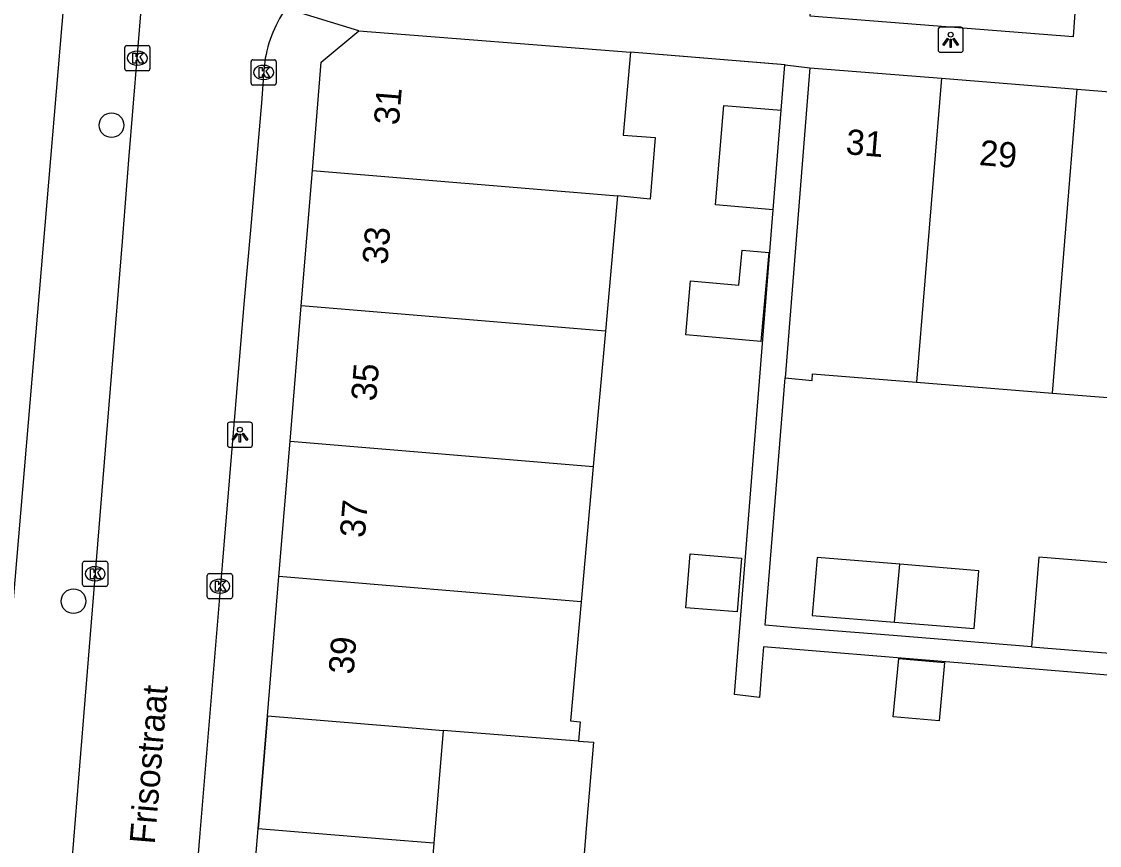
# Model space of a CAD drawing. Extents: x 159961 to 160856, y 382704 to 383353.
# Drawn here: x 160441.41 to 160484.26, y 383165.57 to 383198.31 of the extents above; entities that cross this region are included whole.
import ezdxf

# ---------------------------------------------------------------- set-up
doc = ezdxf.new("R2010")
doc.units = 0
for name, color, linetype in [('IMGEO_Boom', 7, 'Continuous'), ('IMGEO_Kolk', 7, 'Continuous'), ('IMGEO_Lichtpunt', 7, 'Continuous'), ('IMGEO_Muur', 7, 'Continuous'), ('IMGEO_Openbare_ruimte_label', 7, 'Continuous'), ('IMGEO_Pand', 7, 'Continuous'), ('IMGEO_Pand_nummerreeks', 7, 'Continuous'), ('IMGEO_Rijbaan_lokaal_open', 7, 'Continuous'), ('IMGEO_Voetpad_open', 7, 'Continuous')]:
    doc.layers.add(name, color=color, linetype=linetype)

msp = doc.modelspace()

# ---------------------------------------------------------------- linework, layer by layer
at = {"layer": 'IMGEO_Boom'}
for centre in [(160444.987, 383194.191), (160443.476, 383175.277)]:
    msp.add_circle(centre, 0.489, dxfattribs=at)
at = {"layer": 'IMGEO_Kolk'}
for p, q in [((160445.515, 383196.428), (160445.515, 383197.28)), ((160445.59, 383197.354), (160446.442, 383197.354)), ((160446.516, 383197.28), (160446.516, 383196.428)), ((160446.003, 383197.134), (160446.028, 383197.134)), ((160450.608, 383196.788), (160451.46, 383196.788)), ((160446.442, 383196.354), (160445.59, 383196.354)), ((160446.026, 383196.574), (160446.001, 383196.574)), ((160450.533, 383195.862), (160450.533, 383196.714)), ((160451.021, 383196.568), (160451.046, 383196.568)), ((160451.534, 383196.714), (160451.534, 383195.862)), ((160451.044, 383196.008), (160451.019, 383196.008)), ((160451.46, 383195.788), (160450.608, 383195.788)), ((160443.836, 383175.939), (160443.836, 383176.791)), ((160443.911, 383176.865), (160444.763, 383176.865)), ((160444.324, 383176.645), (160444.349, 383176.645)), ((160444.837, 383176.791), (160444.837, 383175.939)), ((160448.794, 383175.447), (160448.794, 383176.299)), ((160448.869, 383176.373), (160449.721, 383176.373)), ((160449.795, 383176.299), (160449.795, 383175.447)), ((160444.763, 383175.865), (160443.911, 383175.865)), ((160444.347, 383176.085), (160444.322, 383176.085)), ((160449.282, 383176.153), (160449.307, 383176.153)), ((160449.721, 383175.373), (160448.869, 383175.373)), ((160449.305, 383175.593), (160449.28, 383175.593))]:
    msp.add_line(p, q, dxfattribs=at)
for points in [[(160445.515, 383196.428), (160445.515, 383197.28)], [(160445.59, 383197.354), (160446.442, 383197.354)], [(160446.516, 383197.28), (160446.516, 383196.428)], [(160445.836, 383197.054), (160445.959, 383197.054), (160445.959, 383196.903), (160446.089, 383197.054), (160446.253, 383197.054), (160446.107, 383196.903), (160446.26, 383196.654), (160446.108, 383196.654), (160446.023, 383196.818), (160445.959, 383196.751), (160445.959, 383196.654), (160445.836, 383196.654), (160445.836, 383197.054)], [(160450.608, 383196.788), (160451.46, 383196.788)], [(160446.442, 383196.354), (160445.59, 383196.354)], [(160450.533, 383195.862), (160450.533, 383196.714)], [(160450.854, 383196.488), (160450.977, 383196.488), (160450.977, 383196.337), (160451.107, 383196.488), (160451.271, 383196.488), (160451.125, 383196.337), (160451.278, 383196.088), (160451.126, 383196.088), (160451.041, 383196.252), (160450.977, 383196.185), (160450.977, 383196.088), (160450.854, 383196.088), (160450.854, 383196.488)], [(160451.534, 383196.714), (160451.534, 383195.862)], [(160451.46, 383195.788), (160450.608, 383195.788)], [(160443.836, 383175.939), (160443.836, 383176.791)], [(160443.911, 383176.865), (160444.763, 383176.865)], [(160444.837, 383176.791), (160444.837, 383175.939)], [(160444.157, 383176.565), (160444.28, 383176.565), (160444.28, 383176.414), (160444.41, 383176.565), (160444.574, 383176.565), (160444.428, 383176.414), (160444.581, 383176.165), (160444.429, 383176.165), (160444.344, 383176.329), (160444.28, 383176.262), (160444.28, 383176.165), (160444.157, 383176.165), (160444.157, 383176.565)], [(160448.794, 383175.447), (160448.794, 383176.299)], [(160448.869, 383176.373), (160449.721, 383176.373)], [(160449.795, 383176.299), (160449.795, 383175.447)], [(160444.763, 383175.865), (160443.911, 383175.865)], [(160449.115, 383176.073), (160449.238, 383176.073), (160449.238, 383175.922), (160449.368, 383176.073), (160449.532, 383176.073), (160449.386, 383175.922), (160449.539, 383175.673), (160449.387, 383175.673), (160449.302, 383175.837), (160449.238, 383175.77), (160449.238, 383175.673), (160449.115, 383175.673), (160449.115, 383176.073)], [(160449.721, 383175.373), (160448.869, 383175.373)]]:
    msp.add_lwpolyline(points, dxfattribs=at)
for centre, start, end in [((160445.592, 383197.278), 91.552, 178.448), ((160445.592, 383197.278), 91.552, 178.448), ((160446.44, 383197.278), 1.552, 88.448), ((160446.44, 383197.278), 1.552, 88.448), ((160450.61, 383196.712), 91.552, 178.448), ((160450.61, 383196.712), 91.552, 178.448), ((160451.458, 383196.712), 1.552, 88.448), ((160451.458, 383196.712), 1.552, 88.448), ((160445.592, 383196.43), 181.552, 268.448), ((160445.592, 383196.43), 181.552, 268.448), ((160446.44, 383196.43), 271.552, 358.448), ((160446.44, 383196.43), 271.552, 358.448), ((160450.61, 383195.864), 181.552, 268.448), ((160450.61, 383195.864), 181.552, 268.448), ((160451.458, 383195.864), 271.552, 358.448), ((160451.458, 383195.864), 271.552, 358.448), ((160443.913, 383176.789), 91.552, 178.448), ((160443.913, 383176.789), 91.552, 178.448), ((160444.761, 383176.789), 1.552, 88.448), ((160444.761, 383176.789), 1.552, 88.448), ((160448.871, 383176.297), 91.552, 178.448), ((160448.871, 383176.297), 91.552, 178.448), ((160449.719, 383176.297), 1.552, 88.448), ((160449.719, 383176.297), 1.552, 88.448), ((160443.913, 383175.941), 181.552, 268.448), ((160443.913, 383175.941), 181.552, 268.448), ((160444.761, 383175.941), 271.552, 358.448), ((160444.761, 383175.941), 271.552, 358.448), ((160448.871, 383175.449), 181.552, 268.448), ((160448.871, 383175.449), 181.552, 268.448), ((160449.719, 383175.449), 271.552, 358.448), ((160449.719, 383175.449), 271.552, 358.448)]:
    msp.add_arc(centre, 0.0765, start, end, dxfattribs=at)
for centre, major_axis, ratio, start_param, end_param in [((160446.002, 383196.854), (-0.387, 0.002), 0.722429, 4.712389, 7.853982), ((160446.027, 383196.854), (-0.39, 0.002), 0.717154, 1.570796, 4.712389), ((160451.02, 383196.288), (-0.387, 0.002), 0.722429, 4.712389, 7.853982), ((160451.045, 383196.288), (-0.39, 0.002), 0.717154, 1.570796, 4.712389), ((160444.323, 383176.365), (-0.387, 0.002), 0.722429, 4.712389, 7.853982), ((160444.348, 383176.365), (-0.39, 0.002), 0.717154, 1.570796, 4.712389), ((160449.281, 383175.873), (-0.387, 0.002), 0.722429, 4.712389, 7.853982), ((160449.306, 383175.873), (-0.39, 0.002), 0.717154, 1.570796, 4.712389)]:
    msp.add_ellipse(centre, major_axis=major_axis, ratio=ratio, start_param=start_param, end_param=end_param, dxfattribs=at)
at = {"layer": 'IMGEO_Lichtpunt'}
for p, q in [((160478.745, 383198.085), (160477.937, 383198.085)), ((160478.745, 383198.085), (160477.937, 383198.085)), ((160477.843, 383197.99), (160477.843, 383197.183)), ((160477.843, 383197.99), (160477.843, 383197.183)), ((160478.839, 383197.183), (160478.839, 383197.99)), ((160478.839, 383197.183), (160478.839, 383197.99)), ((160477.937, 383197.089), (160478.745, 383197.089)), ((160477.937, 383197.089), (160478.745, 383197.089)), ((160449.592, 383182.295), (160449.592, 383181.488)), ((160449.592, 383182.295), (160449.592, 383181.488)), ((160450.494, 383182.39), (160449.686, 383182.39)), ((160450.494, 383182.39), (160449.686, 383182.39)), ((160450.588, 383181.488), (160450.588, 383182.295)), ((160450.588, 383181.488), (160450.588, 383182.295)), ((160449.686, 383181.394), (160450.494, 383181.394)), ((160449.686, 383181.394), (160450.494, 383181.394))]:
    msp.add_line(p, q, dxfattribs=at)
for points in [[(160478.217, 383197.654), (160478.256, 383197.626), (160478.068, 383197.364), (160478.03, 383197.391), (160478.217, 383197.654)], [(160478.319, 383197.606), (160478.366, 383197.606), (160478.366, 383197.284), (160478.319, 383197.284), (160478.319, 383197.606)], [(160478.429, 383197.626), (160478.467, 383197.653), (160478.654, 383197.391), (160478.615, 383197.363), (160478.429, 383197.626)], [(160449.966, 383181.959), (160450.005, 383181.931), (160449.817, 383181.669), (160449.779, 383181.696), (160449.966, 383181.959)], [(160450.068, 383181.911), (160450.115, 383181.911), (160450.115, 383181.589), (160450.068, 383181.589), (160450.068, 383181.911)], [(160450.178, 383181.931), (160450.216, 383181.958), (160450.403, 383181.696), (160450.364, 383181.668), (160450.178, 383181.931)]]:
    msp.add_lwpolyline(points, dxfattribs=at)
for centre in [(160478.342, 383197.788), (160450.091, 383182.093)]:
    msp.add_circle(centre, 0.0994, dxfattribs=at)
for centre, start, end in [((160477.937, 383197.99), 90, 180), ((160477.937, 383197.99), 90, 180), ((160478.745, 383197.99), 0, 90), ((160478.745, 383197.99), 0, 90), ((160477.937, 383197.183), 180, 270), ((160477.937, 383197.183), 180, 270), ((160478.745, 383197.183), 270, 0), ((160478.745, 383197.183), 270, 360), ((160449.686, 383182.295), 90, 180), ((160449.686, 383182.295), 90, 180), ((160450.494, 383182.295), 0, 90), ((160450.494, 383182.295), 0, 90), ((160449.686, 383181.488), 180, 270), ((160449.686, 383181.488), 180, 270), ((160450.494, 383181.488), 270, 0), ((160450.494, 383181.488), 270, 360)]:
    msp.add_arc(centre, 0.0946, start, end, dxfattribs=at)
at = {"layer": 'IMGEO_Muur'}
for points in [[(160471.761, 383196.589), (160465.613, 383197.089)], [(160451.183, 383170.724), (160450.814, 383166.231)]]:
    msp.add_lwpolyline(points, dxfattribs=at)
at = {"layer": 'IMGEO_Pand'}
for points in [[(160452.97, 383192.397), (160453.324, 383196.695), (160454.816, 383197.945)], [(160454.816, 383197.945), (160465.613, 383197.089)], [(160465.613, 383197.089), (160465.318, 383193.797), (160466.602, 383193.697), (160466.395, 383191.25), (160465.102, 383191.386)], [(160472.748, 383196.475), (160471.76, 383184.154)], [(160472.748, 383196.475), (160477.971, 383196.054)], [(160477.971, 383196.054), (160476.986, 383183.979)], [(160477.971, 383196.054), (160483.368, 383195.62)], [(160482.384, 383183.548), (160483.368, 383195.62)], [(160483.368, 383195.62), (160488.765, 383195.185)], [(160471.292, 383190.832), (160469.001, 383191.028), (160469.325, 383194.969), (160471.609, 383194.786)], [(160471.292, 383190.832), (160471.609, 383194.786)], [(160452.526, 383187.016), (160452.97, 383192.397)], [(160452.97, 383192.397), (160465.102, 383191.386)], [(160465.102, 383191.386), (160464.62, 383186.009)], [(160470.8, 383185.597), (160467.811, 383185.865), (160468.003, 383188.006), (160469.925, 383187.835), (160470.05, 383189.225), (160471.117, 383189.129), (160470.8, 383185.597)], [(160452.083, 383181.636), (160452.526, 383187.016)], [(160464.62, 383186.009), (160452.526, 383187.016)], [(160464.62, 383186.009), (160464.138, 383180.631)], [(160471.76, 383184.154), (160472.833, 383184.05), (160472.855, 383184.309), (160476.986, 383183.979)], [(160476.986, 383183.979), (160482.384, 383183.548)], [(160482.384, 383183.548), (160487.781, 383183.118)], [(160451.639, 383176.254), (160452.083, 383181.636)], [(160452.083, 383181.636), (160464.138, 383180.631)], [(160464.138, 383180.631), (160463.656, 383175.254)], [(160469.855, 383174.849), (160467.815, 383175.015), (160467.989, 383177.158), (160470.029, 383176.992), (160469.855, 383174.849)], [(160476.321, 383176.741), (160473.03, 383177.008), (160472.843, 383174.709), (160476.11, 383174.443)], [(160476.11, 383174.443), (160476.321, 383176.741)], [(160476.11, 383174.443), (160479.276, 383174.186), (160479.464, 383176.486), (160476.321, 383176.741)], [(160487.249, 383176.587), (160481.846, 383177.026), (160481.557, 383173.461)], [(160451.183, 383170.724), (160451.639, 383176.254)], [(160463.656, 383175.254), (160451.639, 383176.254)], [(160463.656, 383175.254), (160463.232, 383170.519), (160463.61, 383170.488), (160463.546, 383169.72)], [(160481.557, 383173.461), (160486.958, 383173.022)], [(160477.888, 383170.517), (160476.061, 383170.685), (160476.275, 383173.004), (160478.102, 383172.836), (160477.888, 383170.517)], [(160451.183, 383170.724), (160456.167, 383170.312), (160458.174, 383170.143)], [(160458.174, 383170.143), (160457.795, 383165.655)], [(160463.546, 383169.72), (160458.174, 383170.143)], [(160463.546, 383169.72), (160464.141, 383169.671), (160463.871, 383166.397), (160463.611, 383163.24)], [(160450.358, 383160.699), (160450.814, 383166.231)], [(160457.795, 383165.655), (160455.798, 383165.82), (160450.814, 383166.231)], [(160457.795, 383165.655), (160457.349, 383160.141)]]:
    msp.add_lwpolyline(points, dxfattribs=at)
at = {"layer": 'IMGEO_Rijbaan_lokaal_open'}
for points in [[(160442.381, 383152.727), (160442.403, 383152.848), (160442.458, 383153.658), (160443.021, 383160.036), (160443.691, 383168.249), (160444.785, 383181.786), (160445.421, 383189.575), (160445.681, 383192.81), (160446.195, 383199.097), (160446.213, 383199.341)], [(160451.056, 383196.543), (160450.952, 383195.075), (160450.507, 383190.026), (160450.241, 383187.078), (160449.383, 383176.704), (160448.497, 383166.062), (160447.529, 383154.13), (160447.393, 383152.284)]]:
    msp.add_lwpolyline(points, dxfattribs=at)
msp.add_arc((160455.913, 383196.01), 4.886, 144.8466, 173.7332, dxfattribs=at)
at = {"layer": 'IMGEO_Voetpad_open'}
for points in [[(160439.206, 383153.248), (160444.36, 383214.015)], [(160483.417, 383200.773), (160483.215, 383197.708), (160472.752, 383198.519), (160473.024, 383201.651)], [(160454.816, 383197.945), (160451.918, 383198.823)], [(160471.756, 383196.589), (160465.613, 383197.089)], [(160471.609, 383194.786), (160471.756, 383196.589)], [(160471.756, 383196.589), (160471.761, 383196.589), (160472.748, 383196.475)], [(160485.085, 383172.3), (160470.903, 383173.457), (160470.839, 383172.673), (160470.74, 383171.451), (160469.748, 383171.574), (160471.292, 383190.832)], [(160481.557, 383173.461), (160478.829, 383173.682), (160476.061, 383173.907), (160472.157, 383174.224), (160470.971, 383174.32), (160471.76, 383184.154)], [(160450.814, 383166.231), (160451.183, 383170.724)]]:
    msp.add_lwpolyline(points, dxfattribs=at)

# ---------------------------------------------------------------- texts
at = {"layer": 'IMGEO_Openbare_ruimte_label'}
msp.add_text('Willem Frisostraat', height=1, rotation=85.2411, dxfattribs=at).set_placement((160446.338, 383161.232))
at = {"layer": 'IMGEO_Pand_nummerreeks'}
for s, rotation, p in [('31', 85.2886, (160456.407, 383194.172)), ('31', 355.343, (160474.15, 383193.043)), ('29', 355.343, (160479.453, 383192.611)), ('33', 85.2886, (160455.95, 383188.631)), ('35', 85.2886, (160455.503, 383183.202)), ('37', 85.2886, (160455.055, 383177.774)), ('39', 85.2886, (160454.608, 383172.345))]:
    msp.add_text(s, height=1, rotation=rotation, dxfattribs=at).set_placement(p)

doc.saveas('drawing.dxf')
